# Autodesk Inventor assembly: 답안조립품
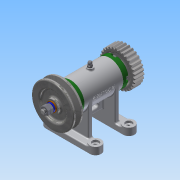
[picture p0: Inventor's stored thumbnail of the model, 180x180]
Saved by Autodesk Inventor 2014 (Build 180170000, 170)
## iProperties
Created: 2015-11
Part Number: 답안조립품
Document SubType Name: Assembly
Designer: 103-09
Author: 103-09
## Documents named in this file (16)
- C:\Users\103-09\Desktop\451110V1016\답안조립품.iam
- C:\Users\103-09\Desktop\451110V1016\1-본체.ipt
- C:\Users\103-09\Desktop\451110V1016\커버.ipt
- C:\Users\103-09\Desktop\451110V1016\베어링 15 x 32 x 9.ipt
- C:\Users\103-09\Desktop\451110V1016\오일 실 15 25 7.ipt
- C:\Users\103-09\Desktop\451110V1016\축.ipt
- C:\Users\103-09\Desktop\451110V1016\와셔 8x17.ipt
- C:\Users\103-09\Desktop\451110V1016\스퍼기어.ipt
- C:\Users\103-09\Desktop\451110V1016\키 3 x 3 x 12.ipt
- C:\Users\103-09\Desktop\451110V1016\스프링와셔 8.ipt
- C:\Users\103-09\Desktop\451110V1016\V벨트풀리.ipt
- C:\Users\103-09\Desktop\451110V1016\너트 M 8.ipt
- C:\Users\103-09\Desktop\451110V1016\니플 M 6 x 0.75.ipt
- C:\Users\103-09\Desktop\451110V1016\와셔 6x11.5.ipt
- C:\Users\103-09\Desktop\451110V1016\볼트 M 6 x 8.ipt
- C:\Users\103-09\Desktop\451110V1016\볼트 M4 x 12.ipt
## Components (12 placed, 4 different names)
1. 1-본체:1
2. KS B 2023 6002 - 15 x 32 x 9:1
3. KS B 2023 6002 - 15 x 32 x 9:2
4. V벨트풀리:1 — 각도:4
5. ISO 4762 M4 x 12:1
6. ISO 4762 M4 x 12:2
7. ISO 4762 M4 x 12:3
8. ISO 4762 M4 x 12:4
9. ISO 4762 M4 x 12:5
10. ISO 4762 M4 x 12:6
11. ISO 4762 M4 x 12:7
12. ISO 4762 M4 x 12:8
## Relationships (1: Angle 1)
- 각도:4 [Angle]: V벨트풀리:1
